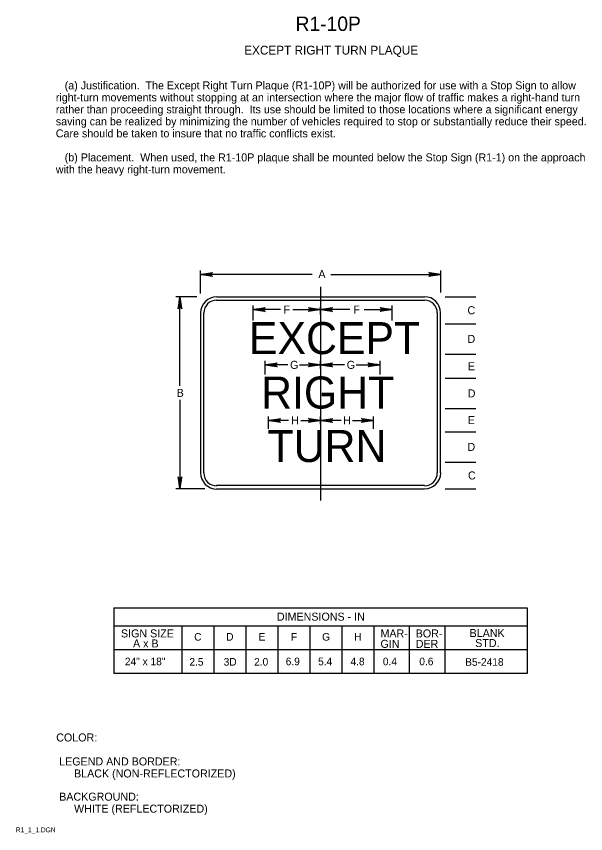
# Model space of a CAD drawing. Extents: x 0.01 to 0.37, y -8.17 to 0.26.
import ezdxf

# ---------------------------------------------------------------- set-up
doc = ezdxf.new("R2010")
doc.units = 0
for name, color, linetype in [('1', 7, 'Continuous'), ('11', 7, 'Continuous'), ('12', 7, 'Continuous'), ('2', 7, 'Continuous'), ('3', 7, 'Continuous')]:
    doc.layers.add(name, color=color, linetype=linetype)

# ---------------------------------------------------------------- blocks, each defined once
blk = doc.blocks.new('RARROW')
at = {"layer": '3'}
for p, q in [((-2.156, 0.285), (-2.2665, 0.384625)), ((-2.2665, 0.384625), (0, 0)), ((0, 0), (-2.2665, -0.379125)), ((-2.156, 0.285), (-2.075625, 0.12075)), ((0, 0), (-2.156, 0.285)), ((-2.14975, -0.2705), (0, 0)), ((-2.075625, 0.12075), (0, 0)), ((0, 0), (-2.074, -0.108)), ((-2.2665, -0.379125), (-2.14975, -0.2705)), ((-2.074, -0.108), (-2.14975, -0.2705))]:
    blk.add_line(p, q, dxfattribs=at)

msp = doc.modelspace()

# ---------------------------------------------------------------- linework, layer by layer
at = {"layer": '1'}
msp.add_line((0.10775, 0.17475), (0.10775, 0.10803), dxfattribs=at)
at = {"layer": '11'}
for p, q in [((0.07025, 0.16668), (0.07025, 0.11668)), ((0.14525, 0.11668), (0.14525, 0.16668)), ((0.07525, 0.11168), (0.14025, 0.11168))]:
    msp.add_line(p, q, dxfattribs=at)
for centre, radius, start, end in [((0.07527, 0.1666), 0.00503, 89.5724, 179.5724), ((0.14022, 0.16668), 0.00503, 0, 90), ((0.07528, 0.11666), 0.00504, 180.2843, 270.2843), ((0.14028, 0.11671), 0.00504, 269.7157, 359.7157)]:
    msp.add_arc(centre, radius, start, end, dxfattribs=at)
at = {"layer": '3'}
for p, q in [((0.07025, 0.17267), (0.07025, 0.17993)), ((0.14538, 0.17305), (0.14538, 0.17993)), ((0.10513, 0.17868), (0.07025, 0.17868)), ((0.111, 0.17868), (0.14538, 0.17868)), ((0.06906, 0.17166), (0.06256, 0.17166)), ((0.06381, 0.14387), (0.06381, 0.17166)), ((0.07531, 0.17166), (0.14023, 0.17166)), ((0.14668, 0.1717), (0.1563, 0.1717)), ((0.07525, 0.17068), (0.14025, 0.17068)), ((0.07531, 0.17062), (0.07525, 0.17064)), ((0.08665, 0.16433), (0.08665, 0.16896)), ((0.10775, 0.1662), (0.10775, 0.16858)), ((0.13017, 0.16433), (0.13017, 0.16896)), ((0.07125, 0.11668), (0.07125, 0.16668)), ((0.09522, 0.16771), (0.08665, 0.16771)), ((0.0991, 0.16771), (0.10775, 0.16771)), ((0.11686, 0.16771), (0.10775, 0.16771)), ((0.12143, 0.16771), (0.13017, 0.16771)), ((0.14425, 0.16668), (0.14425, 0.11668)), ((0.14668, 0.16329), (0.1563, 0.16329)), ((0.14668, 0.15378), (0.1563, 0.15378)), ((0.09045, 0.14739), (0.09045, 0.15167)), ((0.10775, 0.1493), (0.10775, 0.15167)), ((0.12636, 0.14739), (0.12636, 0.15167)), ((0.09753, 0.15042), (0.09045, 0.15042)), ((0.10113, 0.15042), (0.10724, 0.15042)), ((0.11527, 0.15042), (0.1086, 0.15042)), ((0.11893, 0.15042), (0.12636, 0.15042)), ((0.14668, 0.14624), (0.1563, 0.14624)), ((0.06381, 0.13946), (0.06381, 0.11166)), ((0.14668, 0.13677), (0.1563, 0.13677)), ((0.09149, 0.13046), (0.09149, 0.13431)), ((0.09776, 0.13306), (0.09149, 0.13306)), ((0.10154, 0.13306), (0.10775, 0.13306)), ((0.10775, 0.13194), (0.10775, 0.13431)), ((0.11416, 0.13306), (0.10775, 0.13306)), ((0.11772, 0.13306), (0.12431, 0.13306)), ((0.12431, 0.13046), (0.12431, 0.13431)), ((0.14668, 0.12953), (0.1563, 0.12953)), ((0.14668, 0.12006), (0.1563, 0.12006)), ((0.14025, 0.11268), (0.07525, 0.11268)), ((0.07156, 0.11166), (0.06256, 0.11166)), ((0.07906, 0.11166), (0.08806, 0.11166)), ((0.14668, 0.11168), (0.1563, 0.11168)), ((0.04313, 0.0745), (0.04313, 0.054)), ((0.04313, 0.0745), (0.17238, 0.0745)), ((0.17238, 0.0745), (0.17238, 0.054)), ((0.17238, 0.06875), (0.04313, 0.06875)), ((0.06438, 0.06875), (0.06438, 0.054)), ((0.07437, 0.06875), (0.07437, 0.054)), ((0.08438, 0.06875), (0.08438, 0.054)), ((0.09438, 0.06875), (0.09438, 0.054)), ((0.10437, 0.06875), (0.10437, 0.054)), ((0.11438, 0.06875), (0.11438, 0.054)), ((0.12437, 0.06875), (0.12437, 0.054)), ((0.12437, 0.06875), (0.12437, 0.054)), ((0.1355, 0.06875), (0.1355, 0.054)), ((0.14663, 0.06875), (0.14663, 0.054)), ((0.17238, 0.06137), (0.04313, 0.06137)), ((0.17238, 0.054), (0.04313, 0.054))]:
    msp.add_line(p, q, dxfattribs=at)
for centre, radius, start, end in [((0.07527, 0.1666), 0.00403, 89.4662, 179.4662), ((0.14025, 0.16664), 0.004, 360, 90), ((0.07528, 0.11666), 0.00404, 180.3548, 270.3548), ((0.14025, 0.11664), 0.004, 270, 0)]:
    msp.add_arc(centre, radius, start, end, dxfattribs=at)

# ---------------------------------------------------------------- block references
at = {"layer": '3', "xscale": 0.0016545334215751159}
for p, yscale, rotation in [((0.07025, 0.17868), 0.0016366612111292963, 180), ((0.06381, 0.17166), -0.0016366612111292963, 90), ((0.08665, 0.16771), 0.0016366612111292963, 180), ((0.10775, 0.16771), 0.0016366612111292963, 180), ((0.09045, 0.15042), 0.0016366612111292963, 180), ((0.10775, 0.15042), 0.0016366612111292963, 180), ((0.09149, 0.13306), 0.0016366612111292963, 180), ((0.10775, 0.13306), 0.0016366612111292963, 180), ((0.06381, 0.11166), -0.0016366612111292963, -90)]:
    msp.add_blockref('RARROW', p, dxfattribs=dict(at, yscale=yscale, rotation=rotation))
at = {"layer": '3', "xscale": 0.0016545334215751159, "yscale": 0.0016366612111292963}
for p in [(0.14538, 0.17868), (0.10775, 0.16771), (0.13017, 0.16771), (0.10775, 0.15042), (0.12636, 0.15042), (0.10775, 0.13306), (0.12431, 0.13306)]:
    msp.add_blockref('RARROW', p, dxfattribs=at)

# ---------------------------------------------------------------- texts
at = {"layer": '1'}
for s, height, p in [('R1-10P', 0.0045, (0.09995, 0.25475)), ('EXCEPT RIGHT TURN PLAQUE', 0.0027503, (0.08389, 0.24738)), ('COLOR:', 0.0025, (0.02513, 0.03275)), (' LEGEND AND BORDER:', 0.0024998, (0.02513, 0.02525)), ('      BLACK (NON-REFLECTORIZED)', 0.0024998, (0.02513, 0.0215)), (' BACKGROUND:', 0.0024998, (0.02513, 0.01425)), ('      WHITE (REFLECTORIZED)', 0.0024998, (0.02513, 0.0105)), ('R1_1_1.DGN', 0.0015, (0.0125, 0.00438))]:
    msp.add_text(s, height=height, dxfattribs=at).set_placement(p)
at = {"layer": '12'}
for s, p in [('EXCEPT', (0.08538, 0.15379)), ('RIGHT', (0.08918, 0.13677)), ('TURN', (0.09118, 0.12006))]:
    msp.add_text(s, height=0.01, dxfattribs=at).set_placement(p)
at = {"layer": '2'}
for s, height, p in [('   (a) Justification.  The Except Right Turn Plaque (R1-10P) will be authorized for use with a Stop Sign to allow', 0.00249975, (0.025, 0.2365)), ('right-turn movements without stopping at an intersection where the major flow of traffic makes a right-hand turn', 0.00249975, (0.025, 0.23275)), ('rather than proceeding straight through.  Its use should be limited to those locations where a significant energy', 0.00249975, (0.025, 0.229)), ('saving can be realized by minimizing the number of vehicles required to stop or substantially reduce their speed.', 0.00249975, (0.025, 0.22525)), ('Care should be taken to insure that no traffic conflicts exist.', 0.0024998, (0.025, 0.2215)), ('   (b) Placement.  When used, the R1-10P plaque shall be mounted below the Stop Sign (R1-1) on the approach', 0.00249975, (0.025, 0.214)), ('with the heavy right-turn movement.', 0.0024998, (0.025, 0.21025))]:
    msp.add_text(s, height=height, dxfattribs=at).set_placement(p)
at = {"layer": '3'}
for s, height, p in [('A', 0.0025, (0.10707, 0.17752)), ('F', 0.0025, (0.09621, 0.16646)), ('F', 0.0025, (0.11801, 0.16646)), ('C', 0.0025, (0.15368, 0.16624)), ('D', 0.0025, (0.15368, 0.15729)), ('G', 0.0025, (0.09823, 0.14917)), ('G', 0.0025, (0.11593, 0.14917)), ('E', 0.0025, (0.1538, 0.14876)), ('D', 0.0025, (0.15376, 0.14025)), ('H', 0.0025, (0.09859, 0.13181)), ('H', 0.0025, (0.11482, 0.13181)), ('E', 0.0025, (0.15376, 0.1319)), ('D', 0.0025, (0.15367, 0.12355)), ('C', 0.0025, (0.15383, 0.11462)), ('DIMENSIONS - IN', 0.0024998, (0.09411, 0.0705)), ('SIGN SIZE', 0.0025, (0.04537, 0.06525)), ('C', 0.00238, (0.06825, 0.06425)), ('D', 0.00238, (0.07825, 0.06425)), ('E', 0.00238, (0.08837, 0.06425)), ('F', 0.00238, (0.0985, 0.06425)), ('G', 0.00238, (0.10825, 0.06425)), ('H', 0.00238, (0.11825, 0.06425)), ('MAR-', 0.0025, (0.1265, 0.06525)), ('BOR-', 0.0025, (0.1375, 0.06525)), ('BLANK', 0.0025, (0.15434, 0.06538)), ('A x B', 0.0025, (0.04913, 0.06212)), ('GIN', 0.0025, (0.1265, 0.062)), ('DER', 0.0025, (0.1375, 0.062)), ('STD.', 0.0025, (0.15609, 0.06225)), ('24" x 18"', 0.002375, (0.04659, 0.05656)), ('2.5', 0.002375, (0.06675, 0.05644)), ('3D', 0.002375, (0.07747, 0.05644)), ('2.0', 0.002375, (0.08699, 0.05644)), ('6.9', 0.002375, (0.09687, 0.05656)), ('5.4', 0.002375, (0.10698, 0.05656)), ('4.8', 0.002375, (0.11711, 0.05656)), ('0.4', 0.002375, (0.12723, 0.05656)), ('0.6', 0.002375, (0.13862, 0.05656)), ('B5-2418', 0.002375, (0.15296, 0.05639))]:
    msp.add_text(s, height=height, dxfattribs=at).set_placement(p)
msp.add_text('B', height=0.0025, rotation=360, dxfattribs=at).set_placement((0.06278, 0.14042))

doc.saveas('drawing.dxf')
